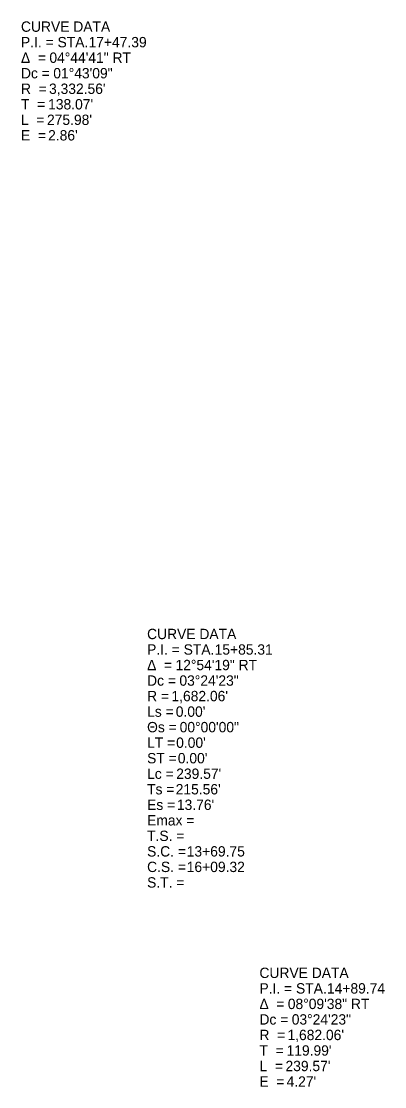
# Model space of a CAD drawing. Extents: x 2283072 to 2287933, y 586198 to 587702.
# Drawn here: x 2285010.3 to 2285108.6, y 586647 to 586935.1 of the extents above; entities that cross this region are included whole.
import ezdxf

# ---------------------------------------------------------------- set-up
doc = ezdxf.new("R2010")
doc.units = 0
doc.layers.add('PV_X_COP', color=7, linetype='Continuous')

msp = doc.modelspace()

# ---------------------------------------------------------------- texts
at = {"layer": 'PV_X_COP'}
for s, p in [('CURVE DATA', (2285010.26, 586932.31)), ('P.I. = STA. ', (2285010.26, 586928.11)), ('17+47.39', (2285028.53, 586928.11)), ('Δ  = ', (2285010.26, 586923.91)), ('04°44\'41" RT', (2285017.94, 586923.91)), ('Dc = ', (2285010.26, 586919.71)), ('01°43\'09"', (2285019, 586919.71)), ('R  = ', (2285010.26, 586915.51)), ("3,332.56'", (2285017.85, 586915.51)), ('T  = ', (2285010.26, 586911.31)), ("138.07'", (2285017.6, 586911.31)), ('L  = ', (2285010.26, 586907.11)), ("275.98'", (2285017.3, 586907.11)), ('E  = ', (2285010.26, 586902.91)), ("2.86'", (2285017.6, 586902.91)), ('CURVE DATA', (2285044.37, 586768.03)), ('P.I. = STA. ', (2285044.37, 586763.83)), ('15+85.31', (2285062.64, 586763.83)), ('Δ  = ', (2285044.37, 586759.63)), ('12°54\'19" RT', (2285052.05, 586759.63)), ('Dc = ', (2285044.37, 586755.43)), ('03°24\'23"', (2285053.11, 586755.43)), ('R = ', (2285044.37, 586751.23)), ("1,682.06'", (2285050.96, 586751.23)), ('Ls = ', (2285044.37, 586747.03)), ("0.00'", (2285052.13, 586747.03)), ('Θs = ', (2285044.37, 586742.83)), ('00°00\'00"', (2285053.18, 586742.83)), ('LT = ', (2285044.37, 586738.63)), ("0.00'", (2285052.23, 586738.63)), ('ST = ', (2285044.37, 586734.43)), ("0.00'", (2285052.68, 586734.43)), ('Lc = ', (2285044.37, 586730.23)), ("239.57'", (2285052.25, 586730.23)), ('Ts = ', (2285044.37, 586726.03)), ("215.56'", (2285052.11, 586726.03)), ('Es = ', (2285044.37, 586721.83)), ("13.76'", (2285052.43, 586721.83)), ('Emax = ', (2285044.37, 586717.63)), ('T.S. = ', (2285044.37, 586713.43)), ('S.C. = ', (2285044.37, 586709.23)), ('13+69.75', (2285055.09, 586709.23)), ('C.S. = ', (2285044.37, 586705.03)), ('16+09.32', (2285055.09, 586705.03)), ('S.T. = ', (2285044.37, 586700.83)), ('CURVE DATA', (2285074.76, 586676.37)), ('P.I. = STA. ', (2285074.76, 586672.17)), ('14+89.74', (2285093.02, 586672.17)), ('Δ  = ', (2285074.76, 586667.97)), ('08°09\'38" RT', (2285082.43, 586667.97)), ('Dc = ', (2285074.76, 586663.77)), ('03°24\'23"', (2285083.49, 586663.77)), ('R  = ', (2285074.76, 586659.57)), ("1,682.06'", (2285082.34, 586659.57)), ('T  = ', (2285074.76, 586655.37)), ("119.99'", (2285082.09, 586655.37)), ('L  = ', (2285074.76, 586651.17)), ("239.57'", (2285081.8, 586651.17)), ('E  = ', (2285074.76, 586646.97)), ("4.27'", (2285082.1, 586646.97))]:
    msp.add_text(s, height=2.8, dxfattribs=at).set_placement(p)

doc.saveas('drawing.dxf')
